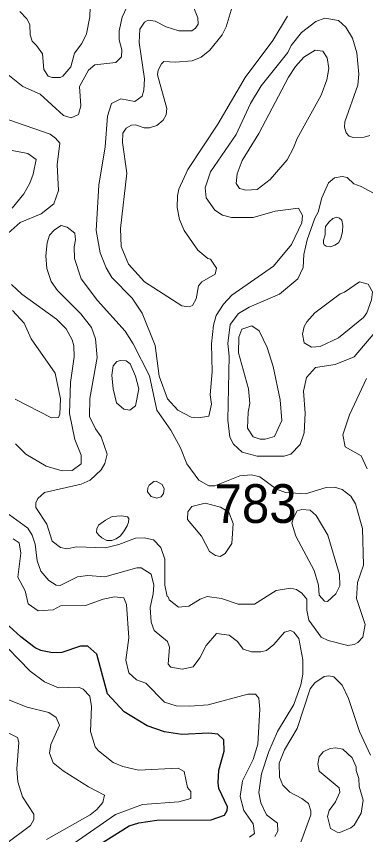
# Model space of a CAD drawing. Extents: x 673.3 to 698.5, y 6984.3 to 7012.3.
# Drawn here: x 674.643 to 675.365, y 6994.934 to 6996.626 of the extents above; entities that cross this region are included whole.
import ezdxf

# ---------------------------------------------------------------- set-up
doc = ezdxf.new("R2010")
doc.units = 0
doc.header["$LTSCALE"] = 0.032
doc.layers.add('1', color=7, linetype='Continuous', lineweight=25)
doc.layers.add('2', color=7, linetype='Continuous', lineweight=13)
doc.layers.add('21', color=7, linetype='Continuous')

msp = doc.modelspace()

# ---------------------------------------------------------------- linework, layer by layer
at = {"layer": '1'}
msp.add_lwpolyline([(674.8094, 6994.9099), (674.8765, 6994.9524), (674.8962, 6994.9581), (674.9331, 6994.9637), (675.0454, 6994.9646), (675.0729, 6994.9741), (675.0783, 6994.9836), (675.079, 6994.9916), (675.0614, 6995.0294), (675.0597, 6995.0413), (675.0612, 6995.0669), (675.0726, 6995.1063), (675.072, 6995.1302), (675.059, 6995.1415), (675.0406, 6995.1437), (674.9848, 6995.1406), (674.9494, 6995.1463), (674.9133, 6995.1591), (674.8659, 6995.1875), (674.8316, 6995.2252), (674.8096, 6995.3072), (674.791, 6995.3235), (674.7755, 6995.3237), (674.7372, 6995.3107), (674.7177, 6995.31), (674.6937, 6995.3143), (674.6823, 6995.3198), (674.6521, 6995.3431), (674.6032, 6995.3867)], dxfattribs=at)
at = {"layer": '2'}
for points in [[(675.1057, 6996.7013), (675.0763, 6996.6038), (675.0684, 6996.5871), (675.0426, 6996.5559), (675.0248, 6996.5414), (675.0064, 6996.5338), (674.9714, 6996.5307), (674.9479, 6996.5322), (674.9426, 6996.5276), (674.9358, 6996.514), (674.935, 6996.5044), (674.9537, 6996.4353), (674.9529, 6996.4219), (674.9463, 6996.411), (674.9331, 6996.4002), (674.9185, 6996.395), (674.9072, 6996.3948), (674.8894, 6996.4011), (674.8813, 6996.4003), (674.8699, 6996.3946), (674.863, 6996.3841), (674.8626, 6996.3646), (674.8715, 6996.3013), (674.8585, 6996.1871), (674.8593, 6996.15), (674.8748, 6996.1129), (674.9081, 6996.0764), (674.9846, 6996.0272), (675.0002, 6996.025), (675.0073, 6996.0281), (675.0148, 6996.0413), (675.0191, 6996.0682), (675.0262, 6996.0768), (675.0536, 6996.0925), (675.0564, 6996.1052), (675.0439, 6996.1233), (675.0388, 6996.1247), (675.0179, 6996.1424), (674.9895, 6996.1831), (674.9802, 6996.2057), (674.975, 6996.2301), (674.9757, 6996.2546), (674.979, 6996.2681), (674.997, 6996.3086), (675.0591, 6996.4025), (675.1159, 6996.4992), (675.1727, 6996.5756), (675.2031, 6996.6262)], [(674.8715, 6996.6446), (674.8615, 6996.6239), (674.8553, 6996.5954), (674.8552, 6996.5773), (674.8608, 6996.5564), (674.8606, 6996.5419), (674.8486, 6996.53), (674.8054, 6996.5251), (674.7924, 6996.5141), (674.7737, 6996.4807), (674.7762, 6996.4407), (674.7717, 6996.4229), (674.7563, 6996.416), (674.7406, 6996.4203), (674.6921, 6996.465), (674.6566, 6996.4802), (674.6149, 6996.5135), (674.606, 6996.5269), (674.5996, 6996.5471), (674.5994, 6996.5757), (674.596, 6996.5878), (674.5504, 6996.6237), (674.5261, 6996.6519)], [(674.6505, 6996.6358), (674.665, 6996.6207), (674.6711, 6996.6085), (674.6719, 6996.5875), (674.6756, 6996.5744), (674.6851, 6996.5654), (674.6969, 6996.5477), (674.6999, 6996.5156), (674.7091, 6996.5017), (674.7174, 6996.4988), (674.7336, 6996.4988), (674.7393, 6996.502), (674.7558, 6996.5211), (674.7633, 6996.5497), (674.7787, 6996.5692), (674.7882, 6996.5895), (674.795, 6996.6246), (674.7959, 6996.6444)], [(675.2037, 6996.5511), (675.1488, 6996.4816), (675.1265, 6996.4456), (675.0974, 6996.381), (675.0439, 6996.3044), (675.0328, 6996.2709), (675.0353, 6996.2504), (675.0533, 6996.2251), (675.069, 6996.2147), (675.0877, 6996.2096), (675.1321, 6996.2098), (675.1777, 6996.2228), (675.2259, 6996.2293), (675.2345, 6996.2138), (675.2329, 6996.1986), (675.2114, 6996.1536), (675.1741, 6996.1093), (675.0879, 6996.049), (675.0708, 6996.0304), (675.0557, 6996.0073), (675.0502, 6995.9873), (675.0461, 6995.9482), (675.0474, 6995.8908), (675.0433, 6995.8429), (675.0465, 6995.824), (675.0407, 6995.799), (675.0193, 6995.7953), (675.0039, 6995.7969), (674.9768, 6995.8113), (674.9553, 6995.8346), (674.9382, 6995.8816), (674.93, 6995.9454), (674.9032, 6996.0119), (674.8826, 6996.0431), (674.8401, 6996.0858), (674.8286, 6996.1057), (674.8163, 6996.1366), (674.808, 6996.1829), (674.8135, 6996.2763), (674.8267, 6996.3558), (674.8315, 6996.4191), (674.8394, 6996.4451), (674.8591, 6996.4547), (674.8882, 6996.4492), (674.9027, 6996.4605), (674.9065, 6996.4732), (674.9081, 6996.4963), (674.8968, 6996.5716), (674.898, 6996.599), (674.9078, 6996.6132), (674.9157, 6996.6176), (674.9296, 6996.6155), (674.9529, 6996.6036), (674.9787, 6996.5958), (675.0055, 6996.5958), (675.0135, 6996.601), (675.0188, 6996.6092), (675.018, 6996.6227), (675.0059, 6996.6533)], [(675.3734, 6996.3793), (675.3614, 6996.3759), (675.339, 6996.3754), (675.3307, 6996.3778), (675.3247, 6996.3844), (675.3211, 6996.3963), (675.3218, 6996.4074), (675.3488, 6996.4833), (675.3503, 6996.5061), (675.3463, 6996.5503), (675.3373, 6996.5803), (675.3234, 6996.6031), (675.3087, 6996.6168), (675.2805, 6996.6218), (675.2614, 6996.6148), (675.2321, 6996.5923), (675.2107, 6996.5654), (675.2037, 6996.5511)], [(674.6275, 6996.4116), (674.7129, 6996.3819), (674.7243, 6996.3739), (674.733, 6996.3634), (674.7273, 6996.3189), (674.7304, 6996.2657), (674.7205, 6996.2381), (674.6942, 6996.2173), (674.6507, 6996.1995), (674.62, 6996.1715)], [(674.6342, 6996.2291), (674.6585, 6996.2588), (674.6711, 6996.2806), (674.6782, 6996.2996), (674.6841, 6996.3299), (674.6672, 6996.3419), (674.6344, 6996.3481)], [(675.3886, 6996.2556), (675.3552, 6996.2741), (675.3404, 6996.2791), (675.3264, 6996.2921), (675.3161, 6996.2944), (675.3003, 6996.2917), (675.2877, 6996.2814), (675.2742, 6996.2502), (675.2665, 6996.2207), (675.2597, 6996.2083), (675.2436, 6996.1633), (675.2372, 6996.133), (675.2357, 6996.1062), (675.2248, 6996.0828), (675.1869, 6996.0511), (675.1239, 6996.024), (675.1022, 6996.0112), (675.0849, 6995.9882), (675.08, 6995.9493), (675.0825, 6995.9232), (675.0799, 6995.7904), (675.0843, 6995.7553), (675.0916, 6995.7413), (675.1099, 6995.7246), (675.1405, 6995.7162), (675.1962, 6995.7164), (675.2104, 6995.7206), (675.2295, 6995.7404), (675.2379, 6995.7643), (675.2396, 6995.8051), (675.2364, 6995.8508), (675.2426, 6995.8786), (675.2613, 6995.8997), (675.3017, 6995.906), (675.3411, 6995.9214), (675.3838, 6995.9718)], [(674.6332, 6996.0714), (674.6542, 6996.0515), (674.7259, 6995.9996), (674.7458, 6995.9796), (674.7581, 6995.9568), (674.7616, 6995.9444), (674.7623, 6995.9217), (674.7551, 6995.8688), (674.7526, 6995.8043), (674.7639, 6995.7507), (674.777, 6995.7187), (674.7771, 6995.7006), (674.7581, 6995.687), (674.7376, 6995.6862), (674.7047, 6995.6953), (674.6628, 6995.7206), (674.6414, 6995.7421)], [(674.6405, 6995.8342), (674.7156, 6995.7953), (674.7301, 6995.7961), (674.7332, 6995.8032), (674.7345, 6995.835), (674.7232, 6995.8878), (674.6735, 6995.9588), (674.659, 6995.9912), (674.6353, 6996.0175)], [(675.368, 6995.6901), (675.3553, 6995.7168), (675.3225, 6995.7353), (675.3178, 6995.7602), (675.3315, 6995.8015), (675.3666, 6995.8767)], [(674.5978, 6995.6171), (674.6671, 6995.5677), (674.6758, 6995.5527), (674.6818, 6995.5343), (674.6859, 6995.4997)], [(674.7857, 6995.4078), (674.7341, 6995.4067), (674.719, 6995.3989), (674.6883, 6995.3963), (674.6677, 6995.4108), (674.6615, 6995.4381), (674.6459, 6995.4663), (674.6524, 6995.5161), (674.6492, 6995.5369), (674.6369, 6995.5451)], [(674.6859, 6995.4997), (674.6936, 6995.4783), (674.7102, 6995.459), (674.7253, 6995.4497), (674.7334, 6995.4488), (674.7695, 6995.4671), (674.791, 6995.4694), (674.8262, 6995.4671), (674.8923, 6995.4858), (674.901, 6995.4856), (674.9216, 6995.4727), (674.9269, 6995.4499), (674.9259, 6995.4314), (674.9196, 6995.4034), (674.9217, 6995.3729), (674.9281, 6995.3559), (674.9552, 6995.3334), (674.9595, 6995.3212), (674.957, 6995.2863), (674.9625, 6995.2803), (674.9859, 6995.2757), (675.0084, 6995.2808), (675.0221, 6995.2993), (675.0353, 6995.3248), (675.0567, 6995.3497), (675.0828, 6995.3463), (675.1001, 6995.3329), (675.1118, 6995.3173), (675.1285, 6995.3116), (675.1484, 6995.3116), (675.1595, 6995.3147), (675.1752, 6995.3271), (675.1968, 6995.3525), (675.2093, 6995.3562), (675.2165, 6995.3525), (675.2267, 6995.3393), (675.2346, 6995.2952), (675.2346, 6995.2659), (675.2307, 6995.2435), (675.2162, 6995.2031), (675.1824, 6995.1468), (675.1644, 6995.1056), (675.1497, 6995.0596), (675.1443, 6995.0207), (675.1482, 6994.9995), (675.1598, 6994.9751), (675.1823, 6994.9573), (675.1833, 6994.941), (675.177, 6994.9298)], [(675.125, 6994.9285), (675.1351, 6994.9361), (675.1321, 6994.9562), (675.1128, 6994.9838), (675.1053, 6995.0129), (675.1102, 6995.045), (675.1323, 6995.089), (675.1417, 6995.1206), (675.1459, 6995.1936), (675.144, 6995.2163), (675.1372, 6995.2244), (675.121, 6995.2244), (675.0395, 6995.2024), (675.0012, 6995.1992), (674.9735, 6995.2), (674.9492, 6995.208), (674.9109, 6995.2468), (674.8914, 6995.2539), (674.8755, 6995.2686), (674.869, 6995.2944), (674.8755, 6995.3405), (674.8705, 6995.4099), (674.8651, 6995.4232), (674.8456, 6995.4258), (674.8225, 6995.4208), (674.7857, 6995.4078)], [(674.6012, 6995.3435), (674.6719, 6995.2715), (674.7015, 6995.25), (674.7301, 6995.2374), (674.7712, 6995.2388), (674.7812, 6995.2347), (674.7948, 6995.2203), (674.7982, 6995.1991), (674.7966, 6995.147), (674.806, 6995.1154), (674.8129, 6995.107), (674.8433, 6995.083), (674.8633, 6995.0749), (674.8953, 6995.0673), (674.9775, 6995.0715), (674.9895, 6995.0644), (674.9969, 6995.0315), (675.0034, 6995.0229), (675.0035, 6995.0083), (674.9786, 6995.0016), (674.9038, 6994.9962), (674.8476, 6994.9754), (674.7202, 6994.8866)], [(675.3749, 6995.0979), (675.352, 6995.147), (675.3291, 6995.2156), (675.3163, 6995.2429), (675.2991, 6995.26), (675.2887, 6995.2625), (675.279, 6995.2611), (675.2597, 6995.2477), (675.25, 6995.2355), (675.2231, 6995.1534), (675.1969, 6995.109), (675.1863, 6995.0818), (675.1866, 6995.0528), (675.1938, 6995.0365), (675.2082, 6995.0214), (675.2331, 6995.0085), (675.2467, 6994.9982), (675.2517, 6994.9828), (675.2516, 6994.975), (675.2281, 6994.9108)], [(674.7056, 6994.9236), (674.7958, 6994.975), (674.8094, 6994.9856), (674.8215, 6995.0005), (674.8249, 6995.0158), (674.7923, 6995.0326), (674.7397, 6995.0657), (674.7193, 6995.0826), (674.7119, 6995.1025), (674.7146, 6995.1199), (674.7322, 6995.16), (674.7254, 6995.1759), (674.7102, 6995.1861), (674.6658, 6995.1974), (674.6253, 6995.2131)], [(674.6034, 6995.1556), (674.6458, 6995.1344), (674.6484, 6995.1243), (674.6443, 6995.0699), (674.6461, 6995.0428), (674.6556, 6995.0121), (674.6792, 6994.9765), (674.6793, 6994.965), (674.6725, 6994.9531), (674.6208, 6994.9141)]]:
    msp.add_lwpolyline(points, dxfattribs=at)
for points in [[(675.2728, 6996.4628), (675.2843, 6996.494), (675.2884, 6996.5179), (675.2851, 6996.5396), (675.2765, 6996.5536), (675.26, 6996.5558), (675.2366, 6996.5414), (675.2196, 6996.5219), (675.205, 6996.5), (675.1442, 6996.3832), (675.1099, 6996.3276), (675.0991, 6996.3001), (675.0971, 6996.28), (675.1041, 6996.2697), (675.117, 6996.266), (675.1405, 6996.2674), (675.1675, 6996.2883), (675.2025, 6996.3292), (675.2158, 6996.3537), (675.2231, 6996.3733)], [(675.3051, 6996.2105), (675.3107, 6996.2086), (675.3151, 6996.2042), (675.3177, 6996.193), (675.3169, 6996.181), (675.3136, 6996.1661), (675.3082, 6996.1576), (675.3008, 6996.1522), (675.2918, 6996.1493), (675.283, 6996.1504), (675.2786, 6996.1532), (675.2774, 6996.1567), (675.2778, 6996.1627), (675.2811, 6996.1742), (675.2811, 6996.1843), (675.282, 6996.191), (675.2895, 6996.201), (675.2965, 6996.2078)], [(675.3455, 6995.4221), (675.3478, 6995.4548), (675.3601, 6995.4908), (675.3584, 6995.5671), (675.3439, 6995.6175), (675.3339, 6995.6334), (675.3164, 6995.6477), (675.3004, 6995.6519), (675.2829, 6995.6518), (675.2402, 6995.6381), (675.1989, 6995.6413), (675.1806, 6995.648), (675.1462, 6995.6734), (675.1288, 6995.6779), (675.1044, 6995.6755), (675.0529, 6995.6552), (675.0408, 6995.6552), (675.0201, 6995.667), (674.9954, 6995.7006), (674.9821, 6995.7337), (674.9622, 6995.7703), (674.9335, 6995.8113), (674.9185, 6995.8822), (674.8845, 6995.9483), (674.8682, 6995.9744), (674.8108, 6996.0384), (674.7772, 6996.083), (674.7631, 6996.1246), (674.7624, 6996.149), (674.7655, 6996.1636), (674.7637, 6996.1773), (674.7484, 6996.1898), (674.7354, 6996.1933), (674.7217, 6996.1844), (674.7119, 6996.173), (674.7067, 6996.1575), (674.7037, 6996.1304), (674.7063, 6996.1041), (674.7151, 6996.0773), (674.7278, 6996.0589), (674.7766, 6996.0107), (674.7981, 6995.9826), (674.8063, 6995.9589), (674.8103, 6995.9201), (674.7949, 6995.8357), (674.7945, 6995.7982), (674.8066, 6995.7726), (674.818, 6995.7564), (674.8306, 6995.7204), (674.8259, 6995.7011), (674.8181, 6995.6878), (674.7956, 6995.6667), (674.7773, 6995.6585), (674.7015, 6995.6409), (674.6876, 6995.6291), (674.6834, 6995.6201), (674.6835, 6995.6104), (674.7061, 6995.5754), (674.7168, 6995.5404), (674.7341, 6995.5277), (674.7471, 6995.5249), (674.7673, 6995.5289), (674.8275, 6995.527), (674.8546, 6995.5337), (674.8895, 6995.5468), (674.9073, 6995.5475), (674.9261, 6995.5432), (674.9415, 6995.5273), (674.9496, 6995.5037), (674.9497, 6995.4493), (674.9546, 6995.4265), (674.9577, 6995.4246), (674.9587, 6995.419), (674.9782, 6995.4044), (674.9991, 6995.4062), (675.0227, 6995.4205), (675.0373, 6995.4264), (675.0667, 6995.4223), (675.1011, 6995.4101), (675.1352, 6995.4104), (675.1796, 6995.4386), (675.2097, 6995.4434), (675.2217, 6995.4409), (675.2331, 6995.4328), (675.2428, 6995.421), (675.2429, 6995.3976), (675.2476, 6995.3773), (675.2725, 6995.3424), (675.2872, 6995.335), (675.3281, 6995.3246), (675.3408, 6995.3267), (675.3487, 6995.3311), (675.3586, 6995.342), (675.3633, 6995.3683)], [(675.3121, 6996.0519), (675.3212, 6996.0552), (675.352, 6996.0769), (675.3699, 6996.0719), (675.3787, 6996.0561), (675.3764, 6996.0394), (675.3669, 6996.0125), (675.3599, 6996.0027), (675.3086, 6995.9612), (675.2708, 6995.9428), (675.2527, 6995.9419), (675.2378, 6995.9505), (675.2339, 6995.9682), (675.2373, 6995.9845), (675.2431, 6995.9943), (675.2596, 6996.0123)], [(675.1255, 6995.8249), (675.1223, 6995.8555), (675.102, 6995.9302), (675.103, 6995.9625), (675.1091, 6995.979), (675.1293, 6995.9859), (675.145, 6995.9752), (675.1615, 6995.9412), (675.1735, 6995.9017), (675.1883, 6995.8325), (675.1916, 6995.7901), (675.1762, 6995.7572), (675.1571, 6995.7513), (675.1468, 6995.7513), (675.1323, 6995.7561), (675.1207, 6995.7744), (675.1222, 6995.8072)], [(674.843, 6995.8558), (674.8405, 6995.8836), (674.8428, 6995.903), (674.8504, 6995.9117), (674.8585, 6995.9141), (674.8702, 6995.9134), (674.8782, 6995.907), (674.8889, 6995.8814), (674.8959, 6995.8558), (674.8893, 6995.8207), (674.8777, 6995.8116), (674.8648, 6995.8133), (674.8502, 6995.8267)], [(674.9173, 6995.6564), (674.9269, 6995.6641), (674.9322, 6995.6648), (674.9443, 6995.6578), (674.9487, 6995.6491), (674.9468, 6995.6394), (674.9423, 6995.6325), (674.9335, 6995.6293), (674.9218, 6995.6326), (674.9141, 6995.6426), (674.9145, 6995.651)], [(674.9976, 6995.6015), (675.0053, 6995.6121), (675.0333, 6995.6194), (675.0648, 6995.6106), (675.0817, 6995.6003), (675.0913, 6995.577), (675.0881, 6995.5358), (675.0744, 6995.5154), (675.0642, 6995.5087), (675.0543, 6995.5112), (675.042, 6995.519), (675.0254, 6995.5509), (674.9969, 6995.5852)], [(675.3104, 6995.4719), (675.2867, 6995.5529), (675.2623, 6995.5933), (675.2502, 6995.6045), (675.2327, 6995.6063), (675.2234, 6995.603), (675.2154, 6995.589), (675.2121, 6995.5775), (675.2207, 6995.5511), (675.2582, 6995.4796), (675.2672, 6995.4499), (675.2689, 6995.429), (675.2797, 6995.4166), (675.2857, 6995.4158), (675.3028, 6995.4316), (675.3112, 6995.4485)], [(674.8729, 6995.5906), (674.8754, 6995.5872), (674.8746, 6995.5796), (674.8721, 6995.5723), (674.8658, 6995.5617), (674.8586, 6995.5514), (674.8495, 6995.5454), (674.8402, 6995.542), (674.8303, 6995.542), (674.8194, 6995.5472), (674.813, 6995.5538), (674.809, 6995.559), (674.8092, 6995.5661), (674.813, 6995.5739), (674.8272, 6995.5843), (674.8412, 6995.5915), (674.86, 6995.5931)], [(675.3023, 6995.0014), (675.3113, 6995.0219), (675.3098, 6995.0307), (675.2685, 6995.0651), (675.2656, 6995.0801), (675.2686, 6995.0944), (675.2766, 6995.105), (675.291, 6995.1119), (675.3032, 6995.1136), (675.3178, 6995.1109), (675.3367, 6995.0927), (675.3453, 6995.074), (675.3447, 6995.0668), (675.3502, 6995.0499), (675.3511, 6995.0333), (675.3592, 6995.0051), (675.3552, 6994.978), (675.3409, 6994.9537), (675.3339, 6994.9478), (675.3112, 6994.9386), (675.3057, 6994.9388), (675.2919, 6994.9467), (675.286, 6994.9714), (675.2893, 6994.9841)]]:
    msp.add_lwpolyline(points, close=True, dxfattribs=at)

# ---------------------------------------------------------------- texts
at = {"layer": '21', "width": 0.95}
msp.add_text('783', height=0.08, dxfattribs=at).set_placement((675.0525, 6995.5784))

doc.saveas('drawing.dxf')
